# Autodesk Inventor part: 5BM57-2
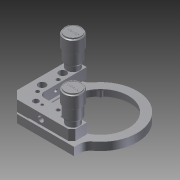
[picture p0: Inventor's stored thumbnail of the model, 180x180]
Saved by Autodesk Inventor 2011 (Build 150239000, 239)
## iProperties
Created: 2011-06
Part Number: 5BM57-2
Document SubType Name: Modeling
Designer: vadybininkas6
Density: 1 g/cm^3
Author: vadybininkas6
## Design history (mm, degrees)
feature "Base1"
body "Solid1"
